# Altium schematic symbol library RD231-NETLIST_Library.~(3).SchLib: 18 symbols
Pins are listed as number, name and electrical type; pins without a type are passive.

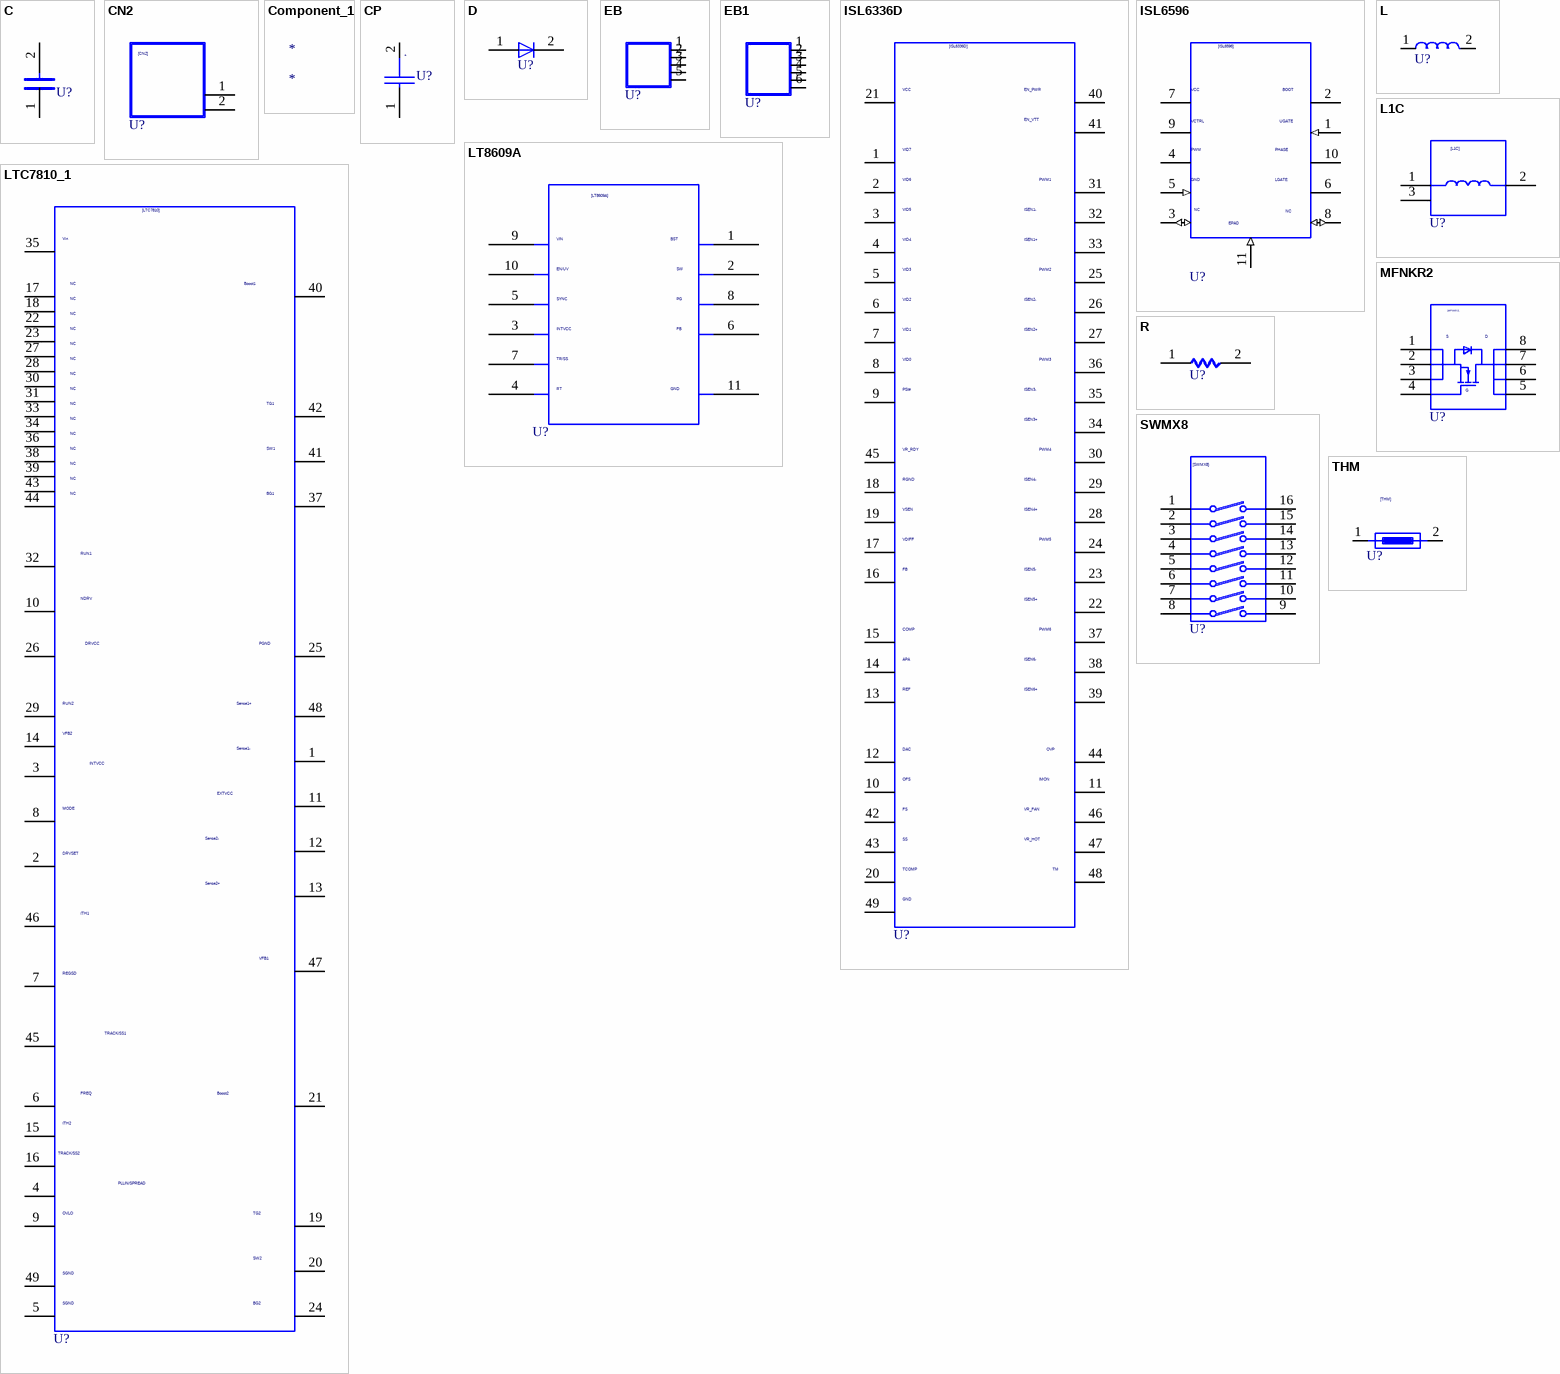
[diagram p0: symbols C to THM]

## C
designator U?  (value not drawn)
OriginalSymbolOrigin: (2540,7620); Altium-Right: 20; Altium-Bottom: 10
pins: 1, 2

## CN2
designator U?  (value not drawn)
OriginalSymbolOrigin: (2540,15240); Altium-Right: 50; Altium-Bottom: 60
pins: 1, 2

## Component_1
designator *

## CP
designator U?  (value not drawn)
SAVEAREA0: -1450,-153,20294,13055; SAVECOUNT: 52; TIME: 15:02:55; UPDATEUSER: fukuda-y; UPDATETIME: 16:13:42; OriginalSymbolOrigin: (2540,10160); Altium-Right: 20
pins: 1, 2

## D
designator U?  (value not drawn)
SAVEAREA0: -225,-91,12804,7836; SAVECOUNT: 3; TIME: 14:49:55; UPDATEUSER: 19870035; UPDATETIME: 14:20:16; OriginalSymbolOrigin: (5080,5080); Altium-Right: 10; Altium-Bottom: 20
pins: 1 A, 2 C

## EB
designator U?  (value not drawn)
SAVEAREA0: -10166,-6669,19798,9727; TIME: 17:33:04; UPDATEUSER: sptcae13; SAVECOUNT: 1; OriginalSymbolOrigin: (0,8890); Altium-Right: 30; Altium-Bottom: 40
pins: 1, 2, 3, 4, 5

## EB1
designator U?  (value not drawn)
SAVEAREA0: -19495,-9575,29572,17273; TIME: 17:33:04; UPDATEUSER: sptcae13; UPDATETIME: 17:37:19; SAVECOUNT: 4; OriginalSymbolOrigin: (0,10160); Altium-Right: 30; Altium-Bottom: 50
pins: 1, 2, 3, 4, 5, 6

## ISL6336D
designator U?  (value not drawn)
TIME: 17:42:33; UPDATEUSER: q91866sr; UPDATETIME: 10:56:10; SAVECOUNT: 140; SAVEAREA0: -131159,-2851,167371,162238; OriginalSymbolOrigin: (5080,152400); Altium-Right: 120; Altium-Bottom: 590
pins: 1, 2, 3, 4, 5, 6, 7, 8, 9, 10, 11, 12, 13, 14, 15, 16, 17, 18, 19, 20, 21, 22, 23, 24, 25, 26, 27, 28, 29, 30, 31, 32, 33, 34, 35, 36, 37, 38, 39, 40, 41, 42, 43, 44, 45, 46, 47, 48, 49

## ISL6596
designator U?  (value not drawn)
PARTS: 1; SAVECOUNT: 32; SAVEAREA0: -56845,-25936,87219,39707; TIME: 14:04:55; UPDATEUSER: sptcae13; UPDATETIME: 17:09:04; DEVICENAME: 74HC244AF; DEVICE: 74VHC245; PKG_TYPE: 20PIN; LEVEL: STD; HETERO: 74VHC245,74VHC245_P; OriginalSymbolOrigin: (5080,27940); Altium-Right: 80; Altium-Bottom: 130
pins: 1 (in), 2, 3 (io), 4, 5 (in), 6, 7, 8 (io), 9, 10, 11 (in)

## L
designator U?  (value not drawn)
OriginalSymbolOrigin: (2540,5080); Altium-Right: 30; Altium-Bottom: 20
pins: 1, 2

## L1C
designator U?  (value not drawn)
SAVECOUNT: 6; SAVEAREA0: -5636,-341,27978,18652; OriginalSymbolOrigin: (5080,15240); Altium-Right: 50
pins: 1, 2, 3

## LT8609A
designator U?  (value not drawn)
TIME: 17:49:40; UPDATEUSER: q91866sr; UPDATETIME: 14:18:47; SAVECOUNT: 44; SAVEAREA0: -19850,-898,65678,46399; OriginalSymbolOrigin: (7620,43180); Altium-Right: 120; Altium-Bottom: 160
pins: 1, 2, 3, 4, 5, 6, 7, 8, 9, 10, 11

## LTC7810_1
designator U?  (value not drawn)
TIME: 17:42:33; UPDATEUSER: q91873sr; UPDATETIME: 00:58:17; SAVECOUNT: 171; SAVEAREA0: -56936,59772,124648,157086; OriginalSymbolOrigin: (5080,193040); Altium-Right: 160; Altium-Bottom: 750
pins: 1, 2, 3, 4, 5, 6, 7, 8, 9, 10, 11, 12, 13, 14, 15, 16, 17, 18, 19, 20, 21, 22, 23, 24, 25, 26, 27, 28, 29, 30, 31, 32, 33, 34, 35, 36, 37, 38, 39, 40, 41, 42, 43, 44, 45, 46, 47, 48, 49

## MFNKR2
designator U?  (value not drawn)
SAVEAREA0: -9199,-39,32138,22820; TIME: 18:57:44; UPDATEUSER: q91866sr; UPDATETIME: 12:36:02; SAVECOUNT: 10; OriginalSymbolOrigin: (5080,20320); Altium-Right: 50; Altium-Bottom: 70
pins: 1, 2, 3, 4, 5, 6, 7, 8

## R
designator U?  (value not drawn)
OriginalSymbolOrigin: (5080,5080); Altium-Right: 20
pins: 1, 2

## SWMX8
designator U?  (value not drawn)
OriginalSymbolOrigin: (5080,30480); Altium-Right: 50; Altium-Bottom: 120
pins: 1, 2, 3, 4, 5, 6, 7, 8, 9, 10, 11, 12, 13, 14, 15, 16

## THM
designator U?  (value not drawn)
SAVECOUNT: 4; SAVEAREA0: -824,-117,15885,10433; TIME: 16:37:29; UPDATEUSER: tomizawa-y; UPDATETIME: 10:51:47; OriginalSymbolOrigin: (2540,5080); Altium-Right: 40; Altium-Bottom: 20
pins: 1, 2

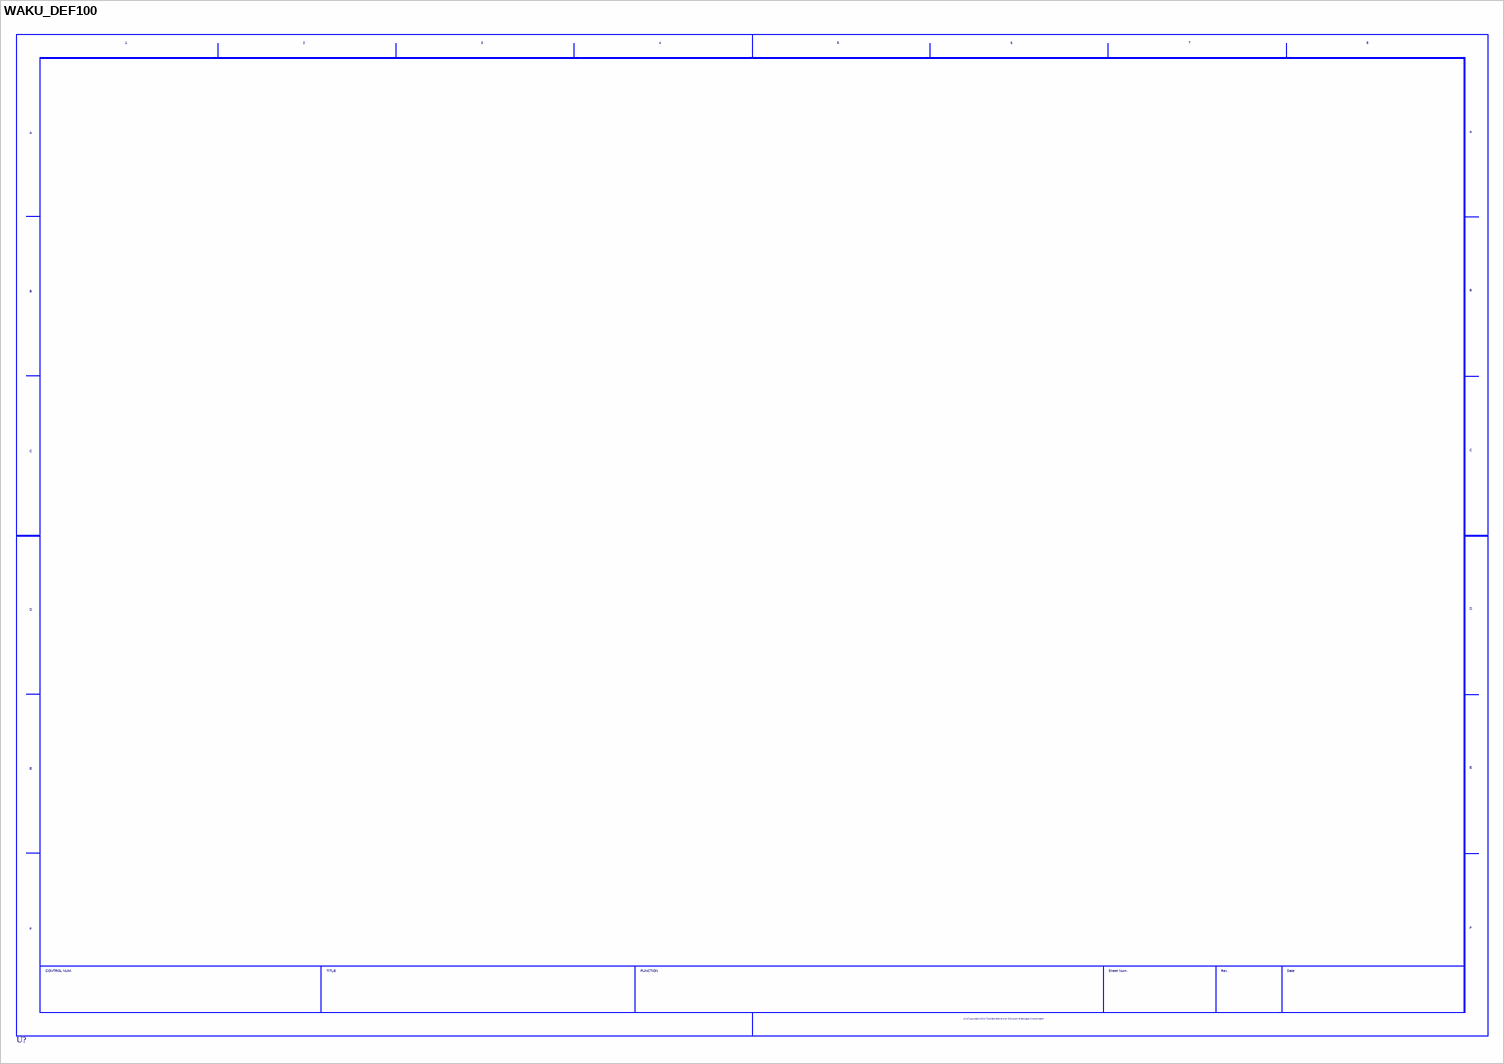
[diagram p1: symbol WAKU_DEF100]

## WAKU_DEF100
designator U?  (value not drawn)
PLOTTIME: HH:MM; SAVEAREA0: 185750,-43960,448537,75779; TIME: 14:30:25; UPDATEUSER: PS4_common_PC; UPDATETIME: 14:13:01; SAVECOUNT: 8; OriginalSymbolOrigin: (10160,284480); Altium-Right: 1570; Altium-Bottom: 1070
